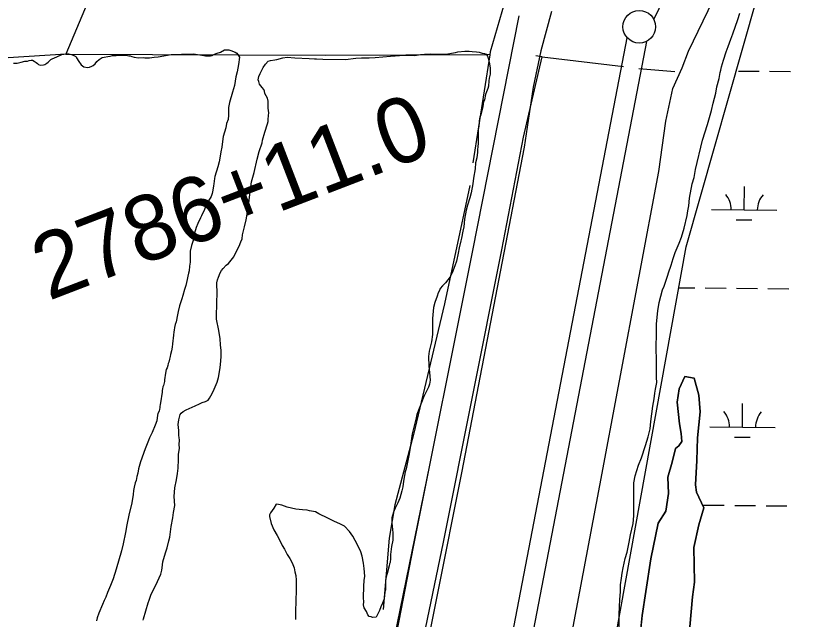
# Model space of a CAD drawing. Extents: x 3271442 to 3309282, y 752266 to 777610.
# Drawn here: x 3284369 to 3285579, y 765185 to 766109 of the extents above; entities that cross this region are included whole.
import ezdxf

# ---------------------------------------------------------------- set-up
doc = ezdxf.new("R2010")
doc.units = 0
for name, color, linetype in [('V-LEVE-TOET', 7, 'Continuous'), ('V-ROAD-CNTR', 7, 'Continuous'), ('V-SITE-VEGE', 7, 'Continuous'), ('V-SURV-IDEN', 7, 'Continuous'), ('V-SURV-LINE', 7, 'Continuous'), ('V-TOPO-SHOR', 7, 'Continuous'), ('V-WETL-SWMP', 7, 'Continuous')]:
    doc.layers.add(name, color=color, linetype=linetype)

msp = doc.modelspace()

# ---------------------------------------------------------------- linework, layer by layer
at = {"layer": 'V-LEVE-TOET'}
for points in [[(3285019.1, 764089.2), (3285037.4, 764155.6), (3285068.7, 764258.4), (3285075.5, 764305.4), (3285079, 764349.1), (3285080.7, 764395.7), (3285086.5, 764454.1), (3285153.1, 764802.6), (3285264, 765389.7), (3285354.1, 765870.7), (3285365.2, 765948), (3285375.6, 765997.9), (3285389.9, 766029.7), (3285399.7, 766055.2), (3285445, 766148.2)], [(3285189.7, 766115.7), (3285173.5, 766055.6), (3285161.9, 765999.9), (3285147.9, 765907.9), (3285052.1, 765409.3), (3284940.1, 764848.3), (3284899.2, 764639.4), (3284846.1, 764357.8), (3284782.6, 764043.9), (3284690.7, 763617), (3284609.2, 763234.1), (3284588.6, 762876.6), (3284537.8, 762620.2), (3284488.8, 762401), (3284437.2, 762116.9), (3284382.2, 761838.2), (3284344.5, 761627.4)]]:
    msp.add_lwpolyline(points, dxfattribs=at)
at = {"layer": 'V-ROAD-CNTR'}
msp.add_lwpolyline([(3285139.8, 766109.2), (3285068, 765747.2), (3284977.9, 765296), (3284933.5, 765066.4), (3284859.7, 764711.2), (3284823.1, 764490.3), (3284745.3, 764120.9), (3284723.5, 764003.4), (3284666.8, 763732.9), (3284607.4, 763402.3), (3284545.6, 763112), (3284510.2, 762930.9), (3284464.6, 762686.8), (3284392.4, 762318.9), (3284315.3, 761934.3)], dxfattribs=at)
at = {"layer": 'V-SITE-VEGE'}
for p, q in [((3285475.5, 766103.3), (3285478.5, 766113)), ((3285467.6, 766081.4), (3285475.5, 766103.3)), ((3285464.7, 766073.6), (3285467.6, 766081.4)), ((3285460.7, 766062), (3285464.7, 766073.6)), ((3285457.3, 766054.2), (3285460.7, 766062)), ((3285453.3, 766041), (3285457.3, 766054.2)), ((3285450.4, 766030.8), (3285453.3, 766041)), ((3285446.9, 766013.3), (3285448.4, 766022.1)), ((3285448.4, 766022.1), (3285449.4, 766026)), ((3285449.4, 766026), (3285450.4, 766030.8)), ((3285443.4, 766000.2), (3285446.9, 766013.3)), ((3285441.9, 765990.9), (3285443.4, 766000.2)), ((3285437.5, 765975.3), (3285441.9, 765990.9)), ((3285435, 765964.1), (3285437.5, 765975.3)), ((3285429.1, 765942.7), (3285435, 765964.1)), ((3285421.2, 765918.9), (3285429.1, 765942.7)), ((3285410.7, 765873.6), (3285421.2, 765918.9)), ((3285408.3, 765861.5), (3285410.7, 765873.6)), ((3285401.3, 765829.8), (3285405.3, 765851.7)), ((3285405.3, 765851.7), (3285408.3, 765861.5)), ((3285400.3, 765818.1), (3285401.3, 765829.8)), ((3285398.8, 765810.3), (3285400.3, 765818.1)), ((3285393.3, 765784.1), (3285397.8, 765803.5)), ((3285397.8, 765803.5), (3285398.8, 765810.3)), ((3285388.9, 765769.9), (3285393.3, 765784.1)), ((3285385.4, 765760.7), (3285388.9, 765769.9)), ((3285379.5, 765746.6), (3285385.4, 765760.7)), ((3285376.1, 765737.4), (3285379.5, 765746.6)), ((3285373.1, 765727.1), (3285376.1, 765737.4)), ((3285369.4, 765715.6), (3285373.1, 765727.1)), ((3285362.3, 765695), (3285368.2, 765712.1)), ((3285368.2, 765712.1), (3285369.4, 765715.6)), ((3285359.8, 765689.2), (3285362.3, 765695)), ((3285354.9, 765670.2), (3285359.8, 765689.2)), ((3285352.9, 765657.1), (3285354.9, 765670.2)), ((3285350.8, 765637.1), (3285352.9, 765657.1)), ((3285350.8, 765624), (3285350.8, 765637.1)), ((3285350.2, 765599.6), (3285350.8, 765624)), ((3285350.6, 765582.1), (3285350.2, 765599.6)), ((3285350.5, 765555.3), (3285350.6, 765582.1)), ((3285351.4, 765547.5), (3285350.5, 765555.3)), ((3285394.4, 765556.9), (3285385.3, 765537.6)), ((3285408.6, 765554), (3285394.4, 765556.9)), ((3285415.4, 765527.9), (3285408.6, 765554)), ((3285348, 765530.9), (3285349, 765537.2)), ((3285349, 765537.2), (3285350.9, 765545)), ((3285350.9, 765545), (3285351.4, 765547.5)), ((3285385.3, 765537.6), (3285382.4, 765517.2)), ((3285347, 765522.6), (3285348, 765530.9)), ((3285417.5, 765502.8), (3285415.4, 765527.9)), ((3285345, 765511), (3285347, 765522.6)), ((3285382.4, 765517.2), (3285386.2, 765484.2)), ((3285341.9, 765487.6), (3285345, 765511)), ((3285413.4, 765462.5), (3285417.5, 765502.8)), ((3285338, 765464.2), (3285340.9, 765476.4)), ((3285340.9, 765476.4), (3285341.9, 765487.6)), ((3285386.2, 765484.2), (3285388.4, 765469.4)), ((3285334, 765451.1), (3285338, 765464.2)), ((3285388.4, 765469.4), (3285389.5, 765456.9)), ((3285389.5, 765456.9), (3285384.9, 765450.7)), ((3285412.7, 765427.9), (3285413.4, 765462.5)), ((3285327.6, 765432.1), (3285334, 765451.1)), ((3285379.8, 765446.2), (3285374.6, 765425.2)), ((3285384.9, 765450.7), (3285379.8, 765446.2)), ((3285323.2, 765420.9), (3285327.6, 765432.1)), ((3285318.2, 765404.4), (3285323.2, 765420.9)), ((3285374.6, 765425.2), (3285368.2, 765402.5)), ((3285410.3, 765390.9), (3285412.7, 765427.9)), ((3285316.2, 765393.7), (3285318.2, 765404.4)), ((3285316, 765343), (3285316.2, 765393.7)), ((3285368.2, 765402.5), (3285369.3, 765377.4)), ((3285411.9, 765379.5), (3285410.3, 765390.9)), ((3285423.2, 765355.6), (3285411.9, 765379.5)), ((3285369.3, 765377.4), (3285365.2, 765350.2)), ((3285415.7, 765329.5), (3285423.2, 765355.6)), ((3285365.2, 765350.2), (3285353.2, 765332.1)), ((3285311, 765314.3), (3285315, 765331.3)), ((3285315, 765331.3), (3285316, 765343)), ((3285353.2, 765332.1), (3285342.2, 765277.5)), ((3285408.2, 765294.9), (3285415.7, 765329.5)), ((3285309, 765303.1), (3285311, 765314.3)), ((3285305.6, 765287.5), (3285309, 765303.1)), ((3285409.1, 765241.5), (3285408.2, 765294.9)), ((3285302.6, 765277.8), (3285305.6, 765287.5)), ((3285299.6, 765263.7), (3285302.6, 765277.8)), ((3285342.2, 765277.5), (3285334.6, 765227.6)), ((3285298.1, 765255.4), (3285299.6, 765263.7)), ((3285295.6, 765237.4), (3285297.1, 765247.6)), ((3285297.1, 765247.6), (3285298.1, 765255.4)), ((3285295.6, 765226.7), (3285295.6, 765237.4)), ((3285406.1, 765219.3), (3285409.1, 765241.5)), ((3285294.6, 765215), (3285295.6, 765226.7)), ((3285334.6, 765227.6), (3285328.7, 765190.6)), ((3285293.5, 765192.6), (3285294.6, 765215)), ((3285402, 765173.3), (3285406.1, 765219.3)), ((3285293.3, 765158), (3285293.5, 765192.6)), ((3285328.7, 765190.6), (3285324.6, 765149.7))]:
    msp.add_line(p, q, dxfattribs=at)
for points in [[(3284452.1, 766050.4), (3284454.1, 766050.1), (3284458.5, 766048.1), (3284460.6, 766046.7), (3284461.8, 766045), (3284465.4, 766039.2), (3284468.7, 766034.3), (3284470.8, 766032.3), (3284472.8, 766031.2), (3284478.4, 766030.1), (3284481.9, 766030.4), (3284485.4, 766031.9), (3284487.4, 766033.2), (3284490.6, 766035.8), (3284493.1, 766039.4), (3284496.3, 766042.4), (3284501.2, 766045.4), (3284504.1, 766045.7), (3284509.7, 766046.7), (3284513.2, 766047.6), (3284517.2, 766048.2), (3284522.5, 766048.3), (3284533.3, 766049.1), (3284539.7, 766048.6), (3284541.8, 766048.1), (3284544.1, 766047.8), (3284546.5, 766047), (3284550.3, 766045.9), (3284556.7, 766044.8), (3284564.6, 766045.5), (3284566.6, 766045), (3284570.1, 766044.8), (3284573.6, 766044.8), (3284580.9, 766045.8), (3284586.8, 766046.5), (3284601, 766049.1), (3284606.9, 766049.7), (3284613, 766049.8), (3284622.9, 766050.6), (3284641.3, 766050.9), (3284657.1, 766048.5), (3284659.7, 766047.7), (3284667, 766047.8), (3284669.7, 766048.5), (3284673.1, 766050.3), (3284677.2, 766051.8), (3284682.7, 766053.3), (3284688.5, 766056.9), (3284695.5, 766057.1), (3284698.4, 766056.2), (3284704.9, 766053.7), (3284707.3, 766052), (3284711.5, 766045.7), (3284710.2, 766034.8), (3284708, 766023.4), (3284706.1, 766015.8), (3284705.1, 766009.3), (3284703.7, 766002.3), (3284701, 765992.3), (3284696.3, 765976.2), (3284694.9, 765968.9), (3284694.8, 765956.9), (3284694.1, 765950.2), (3284691.8, 765944.3), (3284690.5, 765937.8), (3284686.6, 765924.1), (3284686.1, 765920.5), (3284684.6, 765908), (3284682.9, 765900.9), (3284681.3, 765891.3), (3284680.3, 765885.7), (3284678.3, 765877.8), (3284673.9, 765863.1), (3284673.4, 765860.2), (3284672.4, 765851.7), (3284671.5, 765848.5), (3284670.8, 765842.3), (3284669.7, 765837), (3284668, 765832.3), (3284666.9, 765829.7), (3284660.3, 765819.9), (3284657.8, 765812.6), (3284653.6, 765802.9), (3284651.6, 765799.9), (3284647.7, 765790.8), (3284645.4, 765784.7), (3284642.7, 765776.1), (3284641.9, 765770), (3284639.4, 765762.1), (3284638, 765757.1), (3284636.1, 765748.6), (3284636.2, 765741.9), (3284635.8, 765731.6), (3284635, 765725.8), (3284634.3, 765718.5), (3284633.5, 765714.7), (3284632.4, 765710.6), (3284631.3, 765705), (3284629.1, 765695.9), (3284627.2, 765690), (3284625, 765680.7)], [(3284365.3, 766036.4), (3284370.8, 766036.8), (3284376.9, 766038.3), (3284382.8, 766039.6), (3284386.8, 766039.9), (3284389.2, 766040.6), (3284392.1, 766041.2), (3284394.1, 766041.2), (3284396.8, 766039.8), (3284399.7, 766037.5), (3284401.8, 766036.1), (3284403.6, 766034.7), (3284406.2, 766033.8), (3284411.2, 766033.9), (3284413.2, 766034.8), (3284416.1, 766036.6), (3284418.4, 766038.4), (3284420.1, 766039.6), (3284422.4, 766042), (3284424.7, 766043.5), (3284431.4, 766046.5), (3284439.2, 766049.9), (3284442.4, 766050.5), (3284445.9, 766050.9), (3284450, 766050.9), (3284452.1, 766050.4)], [(3284755.7, 766039.5), (3284759.1, 766040.5), (3284765.9, 766041.9), (3284768.9, 766042.4), (3284778.1, 766044.8), (3284784.5, 766045.7), (3284796.2, 766044.7), (3284818.6, 766043.6), (3284826.4, 766043.1), (3284829.8, 766043.1), (3284839.5, 766042.6), (3284874.1, 766042.4), (3284889.7, 766044.3), (3284898.5, 766044.8), (3284910.2, 766044.7), (3284919.4, 766045.2), (3284942.8, 766047.5), (3284963.8, 766048.9), (3284973, 766048.8), (3284979.8, 766048.3), (3284989.1, 766049.8), (3284995.4, 766050.2), (3285004.7, 766050.7), (3285028.1, 766050.6), (3285042.7, 766052.9), (3285046.1, 766053.9), (3285056.8, 766054.8), (3285063.6, 766054.8), (3285068, 766054.3), (3285074.9, 766053.8), (3285078.7, 766053.3), (3285083.6, 766051.8), (3285087, 766051.3), (3285089.5, 766050.3), (3285091.9, 766047.4), (3285092.8, 766044.5), (3285094.8, 766035.7), (3285095.7, 766028.9), (3285095.7, 766019.6), (3285094.2, 766013.8), (3285093.7, 766009.4), (3285093.1, 766001.6), (3285092.2, 765997.7), (3285090.2, 765992.8), (3285088.7, 765988.4), (3285087.2, 765980.7), (3285085.7, 765977.7), (3285084.7, 765969.5), (3285082.8, 765964.1), (3285081.3, 765957.3), (3285079.8, 765953.9), (3285078.8, 765948.5), (3285078.8, 765945.6), (3285078.3, 765940.3), (3285077.3, 765934.9), (3285077.2, 765914.4), (3285076.7, 765908.1), (3285076.2, 765904.7), (3285076.2, 765900.3), (3285075.2, 765891.6), (3285073.2, 765883.8), (3285072.7, 765875), (3285070.2, 765860.4), (3285069.2, 765851.6), (3285066.7, 765838), (3285064.7, 765830.2), (3285061.2, 765819), (3285059.2, 765811.7), (3285056.3, 765797.6), (3285055.2, 765785.9), (3285053.8, 765779.1), (3285051.8, 765768.4), (3285050.8, 765764.5), (3285048.3, 765753.8), (3285046.8, 765745.5), (3285044.3, 765733.4), (3285041.8, 765726.1), (3285037.4, 765715.4), (3285034.5, 765709.5), (3285027.6, 765700.3), (3285022.7, 765695.4), (3285019.3, 765691.6), (3285018.3, 765688.6)], [(3284576, 765223.3), (3284583.4, 765237.3), (3284591.2, 765253.9), (3284592.7, 765260.2), (3284593.2, 765263.6), (3284594.2, 765272.9), (3284598.2, 765286.5), (3284600.7, 765294.3), (3284603.1, 765305), (3284604.6, 765310.8), (3284606.1, 765318.6), (3284607.1, 765326.9), (3284609.6, 765340), (3284610.6, 765348.3), (3284612.6, 765359), (3284611.7, 765372.7), (3284612.7, 765386.3), (3284615.2, 765398.5), (3284616.7, 765408.2), (3284617.7, 765416.5), (3284618.3, 765429.6), (3284618.3, 765437.4), (3284619.8, 765446.7), (3284619.3, 765452.5), (3284619.4, 765459.4), (3284618.9, 765463.2), (3284618.4, 765466.2), (3284618.4, 765474), (3284617.5, 765483.2), (3284618.5, 765490.5), (3284620.5, 765498.3), (3284622, 765500.3), (3284625.4, 765503.2), (3284629.8, 765505.6), (3284643.4, 765511.9), (3284650.3, 765514.8), (3284654.2, 765516.7), (3284659.5, 765518.6), (3284663.5, 765520.6), (3284665.4, 765523.5), (3284669.8, 765530.8), (3284672.8, 765537.1), (3284677.2, 765547.8), (3284679.2, 765555.1), (3284681.7, 765566.8), (3284682.7, 765574.6), (3284683.7, 765587.2), (3284683.7, 765596.5), (3284682.3, 765605.2), (3284681.9, 765614.5), (3284680, 765627.2), (3284676.6, 765644.7), (3284676.7, 765673), (3284677.3, 765681.3), (3284677.3, 765687.6), (3284676.8, 765695.9), (3284676.9, 765700.3), (3284677.8, 765704.6), (3284679.3, 765709), (3284681.8, 765715.3), (3284683.8, 765718.8), (3284686.7, 765722.1), (3284691.1, 765727), (3284695, 765729.9), (3284702.8, 765740.1), (3284708.7, 765751.8), (3284711.2, 765756.1), (3284713.6, 765763), (3284715.6, 765767.3), (3284716.1, 765773.7), (3284719.1, 765785.8), (3284721.6, 765796.5), (3284725.6, 765817.5), (3284727.1, 765831.6), (3284730.1, 765855), (3284734.1, 765869.1), (3284738.5, 765889.5), (3284742, 765901.2), (3284746.4, 765914.8), (3284746.9, 765918.7), (3284750.4, 765930.9), (3284754.3, 765943.5), (3284755.3, 765947.4), (3284755.3, 765950.3), (3284756.3, 765956.7), (3284756.4, 765960.6), (3284755.4, 765967.9), (3284755.4, 765978.6), (3284754.5, 765983), (3284750.6, 765990.3), (3284749.7, 765993.7), (3284748.7, 765996.2), (3284746.3, 765999.1), (3284742.4, 766004.5), (3284741.4, 766008.4), (3284740, 766011.3), (3284741, 766016.2), (3284743.4, 766020.6), (3284747.9, 766029.8), (3284751.3, 766035.1), (3284755.7, 766039.5)], [(3285018.3, 765688.6), (3285015.9, 765684.8), (3285014.4, 765679.9), (3285010.9, 765670.2), (3285008.9, 765662.4), (3285007.4, 765645.3), (3285007.3, 765621), (3285005.8, 765609.8), (3285002.3, 765595.7), (3285001.3, 765587.4), (3285001.8, 765572.3), (3285002.7, 765563), (3285003.6, 765551.3), (3285002.6, 765545), (3285001.1, 765540.1), (3284998.7, 765535.3), (3284994.3, 765526), (3284986.9, 765507.5), (3284983.4, 765498.3), (3284982.4, 765493.4), (3284976.5, 765469.1), (3284973.5, 765451.1), (3284971.5, 765438.4), (3284967, 765415.1), (3284965.5, 765410.7), (3284963, 765396.1), (3284962, 765387.8), (3284960.5, 765381.5), (3284957.1, 765370.3), (3284954.1, 765363), (3284950.2, 765355.2), (3284947.7, 765348.9), (3284945.3, 765340.1), (3284945.2, 765332.3), (3284946.6, 765317.2), (3284946.6, 765306), (3284944.6, 765296.3), (3284943.1, 765284.1), (3284943.1, 765277.8), (3284942.6, 765271.9), (3284941.6, 765269.5), (3284941.1, 765266.6), (3284939.6, 765261.2), (3284938.6, 765256.4), (3284937.1, 765252), (3284935.6, 765244.7), (3284935.6, 765230.1), (3284934.6, 765226.7), (3284934.1, 765221.3), (3284933.1, 765216), (3284931.6, 765212.1), (3284930.6, 765209.6), (3284928.2, 765203.8), (3284926.2, 765198), (3284922.7, 765191.1), (3284921.3, 765188.2), (3284915.4, 765187.3), (3284913.5, 765188.3), (3284910.6, 765189.2), (3284908.1, 765191.7), (3284906.2, 765196.6), (3284902.8, 765202.4), (3284901.9, 765206.8), (3284902.4, 765211.7), (3284901.9, 765217.5), (3284902, 765235.6), (3284902.5, 765244.3), (3284903.5, 765250.7), (3284902.6, 765262.4), (3284901.6, 765270.6), (3284899.7, 765281.4), (3284897.8, 765288.2), (3284892.5, 765298.9), (3284885.2, 765312.1), (3284880.4, 765319), (3284872.6, 765327.3), (3284866.3, 765330.7), (3284856.1, 765335.1), (3284846.9, 765339.6), (3284833.3, 765346.4), (3284827.9, 765349.4), (3284819.1, 765350.9), (3284815.2, 765351.9), (3284808.4, 765352.4), (3284798.2, 765353.4), (3284784.6, 765356.4), (3284776.3, 765359.8), (3284771.4, 765360.8), (3284768, 765361.3), (3284764.1, 765355), (3284759.2, 765347.7), (3284757.7, 765344.8), (3284757.7, 765342.4), (3284760.1, 765331.6), (3284764, 765321.9), (3284769.3, 765313.1), (3284774.6, 765303.3), (3284777, 765297.9), (3284780.4, 765292.1), (3284784.8, 765283.8), (3284788.6, 765277.9)], [(3284625, 765680.7), (3284623, 765675.7), (3284619.7, 765665.1), (3284617.5, 765656.3), (3284616.4, 765651.3), (3284614.3, 765640.5), (3284613.2, 765636.4), (3284611.8, 765631.7), (3284611.3, 765627.6), (3284611, 765625.2), (3284610.5, 765620), (3284609, 765606.5), (3284608.2, 765601.8), (3284607.4, 765596), (3284605.8, 765590.4), (3284605.2, 765587.5), (3284604.1, 765583.4), (3284603.3, 765578.7), (3284602.5, 765576.6), (3284601.7, 765573.4), (3284600.8, 765570.2), (3284599.4, 765567.2), (3284598.3, 765561.9), (3284596.8, 765551.4), (3284596.5, 765549.1), (3284594.9, 765542.9), (3284594.3, 765540.9), (3284593.8, 765537.6), (3284593, 765535.3), (3284593, 765532.4), (3284592.5, 765529.7)], [(3284592.5, 765529.7), (3284591.2, 765519.5), (3284590.1, 765513.9), (3284589.6, 765510.7), (3284589.3, 765508.6), (3284588.8, 765506.6), (3284588.5, 765503.7), (3284586.2, 765500.1), (3284585.9, 765497.3), (3284584.8, 765488.9), (3284582.6, 765481.9), (3284577.8, 765470.9), (3284573.7, 765462.8), (3284571.9, 765458.4), (3284567.1, 765445.9), (3284559.7, 765426), (3284556.7, 765415), (3284555.9, 765408.7), (3284554.5, 765403.6), (3284553, 765397.3), (3284551.5, 765394), (3284550.4, 765387.4), (3284548.9, 765381.9), (3284548.5, 765376), (3284546.7, 765363.1), (3284541.9, 765344.3), (3284538.9, 765329.3), (3284537, 765317.9), (3284533.3, 765300.6), (3284530.7, 765289.5), (3284522.6, 765261.6), (3284517.8, 765246.5), (3284514.1, 765236.6), (3284509.3, 765225.9), (3284506.7, 765218.9), (3284504.1, 765213.4), (3284501.5, 765207.5), (3284496, 765194.3), (3284493.4, 765186.9), (3284492.3, 765182.5)], [(3284788.6, 765277.9), (3284792.5, 765271.1), (3284795.4, 765263.8), (3284796.4, 765257.4), (3284797.8, 765252.1), (3284798.7, 765244.8), (3284798.7, 765226.7), (3284798.1, 765215.5), (3284798.1, 765208.7), (3284797.6, 765201.4), (3284797.5, 765184.3)], [(3284563.7, 765183.4), (3284564.7, 765185.3), (3284571.6, 765210.1), (3284573.1, 765214), (3284576, 765223.3)]]:
    msp.add_lwpolyline(points, dxfattribs=at)
at = {"layer": 'V-SURV-LINE'}
for points in [[(3285836.9, 767117.4), (3285346.5, 766103.9)], [(3284930.7, 764126.5), (3285305.8, 766075.6)], [(3285335.2, 766070), (3284960.2, 764120.8)]]:
    msp.add_lwpolyline(points, dxfattribs=at)
msp.add_circle((3285324.3, 766092.4), 25, dxfattribs=at)
at = {"layer": 'V-TOPO-SHOR'}
for p, q in [((3285095.4, 766049.4), (3285069, 765883.8)), ((3285175.6, 766046.2), (3285300, 766031.3)), ((3285323.5, 766028.4), (3285378.8, 766023.8)), ((3285002.9, 765420.7), (3284910.7, 764970.3))]:
    msp.add_line(p, q, dxfattribs=at)
for points in [[(3284735.1, 766740.1), (3284604.3, 766428.3), (3284445.3, 766050.6), (3284843.3, 766049.1), (3285089.6, 766049.9)], [(3285117.3, 766127.5), (3285095.9, 766053.8), (3285095.4, 766049.4), (3285089.6, 766049.9)], [(3284445.3, 766050.6), (3284357, 766045), (3284177.2, 766036)], [(3284706.9, 763751.2), (3284765.9, 764026.2), (3284777, 764038.5), (3284790.1, 764111.8), (3284798.7, 764153.2), (3284808.9, 764205.7), (3284806.2, 764218.2), (3284807.8, 764243.1), (3284816.4, 764277.6), (3284859.7, 764497.3), (3284898.6, 764686.6), (3284931.9, 764858), (3285024.1, 765302.9), (3285113.6, 765750.5), (3285146.9, 765923.3), (3285175.6, 766046.2), (3285165.9, 766047.7)], [(3285064.6, 765849.2), (3285025.7, 765668.2), (3284978.4, 765467.9), (3284949.9, 765360.2), (3284941.1, 765309.1), (3284931.9, 765199.8)], [(3285324.6, 765149.7), (3285328.7, 765190.6), (3285334.6, 765227.6), (3285342.2, 765277.5), (3285353.2, 765332.1), (3285365.2, 765350.2), (3285369.3, 765377.4), (3285368.2, 765402.5), (3285374.6, 765425.2), (3285379.8, 765446.2), (3285384.9, 765450.7), (3285389.5, 765456.9), (3285388.4, 765469.4), (3285386.2, 765484.2), (3285382.4, 765517.2), (3285385.3, 765537.6), (3285394.4, 765556.9), (3285408.6, 765554), (3285415.4, 765527.9), (3285417.5, 765502.8), (3285413.4, 765462.5), (3285412.7, 765427.9), (3285410.3, 765390.9), (3285411.9, 765379.5), (3285423.2, 765355.6), (3285415.7, 765329.5), (3285408.2, 765294.9), (3285409.1, 765241.5), (3285406.1, 765219.3), (3285402, 765173.3)]]:
    msp.add_lwpolyline(points, dxfattribs=at)
at = {"layer": 'V-WETL-SWMP'}
for p, q in [((3285396.2, 765755.2), (3285509.7, 766153.1)), ((3285476.2, 766024.6), (3285508.2, 766024.3)), ((3285524.2, 766024.2), (3285556.2, 766023.9)), ((3285485.2, 765811.9), (3285485.5, 765847.9)), ((3285435.3, 765812.3), (3285535.2, 765811.5)), ((3285473.1, 765796.5), (3285497.1, 765796.4)), ((3285197.4, 764656.2), (3285396.2, 765755.2)), ((3285384.8, 765692.6), (3285409.4, 765692.4)), ((3285425.4, 765692.3), (3285457.4, 765692)), ((3285473.4, 765691.9), (3285505.4, 765691.6)), ((3285521.4, 765691.5), (3285553.4, 765691.2)), ((3285394.4, 765556.9), (3285385.3, 765537.6)), ((3285408.6, 765554), (3285394.4, 765556.9)), ((3285415.4, 765527.9), (3285408.6, 765554)), ((3285385.3, 765537.6), (3285382.4, 765517.2)), ((3285417.5, 765502.8), (3285415.4, 765527.9)), ((3285382.4, 765517.2), (3285386.2, 765484.2)), ((3285482.5, 765479.2), (3285482.8, 765515.2)), ((3285413.4, 765462.5), (3285417.5, 765502.8)), ((3285386.2, 765484.2), (3285388.4, 765469.4)), ((3285432.5, 765479.6), (3285532.5, 765478.8)), ((3285388.4, 765469.4), (3285389.5, 765456.9)), ((3285389.5, 765456.9), (3285384.9, 765450.7)), ((3285412.7, 765427.9), (3285413.4, 765462.5)), ((3285470.4, 765463.9), (3285494.4, 765463.7)), ((3285379.8, 765446.2), (3285374.6, 765425.2)), ((3285384.9, 765450.7), (3285379.8, 765446.2)), ((3285374.6, 765425.2), (3285368.2, 765402.5)), ((3285410.3, 765390.9), (3285412.7, 765427.9)), ((3285368.2, 765402.5), (3285369.3, 765377.5)), ((3285411.9, 765379.5), (3285410.3, 765390.9)), ((3285423.2, 765355.6), (3285411.9, 765379.5)), ((3285369.3, 765377.5), (3285365.2, 765350.2)), ((3285415.7, 765329.5), (3285423.2, 765355.6)), ((3285422.7, 765359.6), (3285454.7, 765359.4)), ((3285470.7, 765359.2), (3285502.7, 765359)), ((3285518.7, 765358.8), (3285550.7, 765358.6)), ((3285365.2, 765350.2), (3285353.2, 765332.1)), ((3285353.2, 765332.1), (3285342.2, 765277.5)), ((3285408.2, 765294.9), (3285415.7, 765329.5)), ((3285409.1, 765241.5), (3285408.2, 765294.9)), ((3285342.2, 765277.5), (3285334.6, 765227.6)), ((3285406.1, 765219.3), (3285409.1, 765241.5)), ((3285334.6, 765227.6), (3285328.7, 765190.6)), ((3285402, 765173.3), (3285406.1, 765219.3)), ((3285328.7, 765190.6), (3285324.6, 765149.7))]:
    msp.add_line(p, q, dxfattribs=at)
for centre, start, end in [((3285430, 765812.8), 358.7563, 40.2999), ((3285540.5, 765811.9), 138.7563, 180.2999), ((3285427.3, 765480.1), 358.7563, 40.2999), ((3285537.8, 765479.2), 138.7563, 180.2999)]:
    msp.add_arc(centre, 35.2, start, end, dxfattribs=at)

# ---------------------------------------------------------------- texts
at = {"layer": 'V-SURV-IDEN'}
msp.add_text('2786+11.0', height=100, rotation=21.0359, dxfattribs=at).set_placement((3284418.9, 765672.2))

doc.saveas('drawing.dxf')
